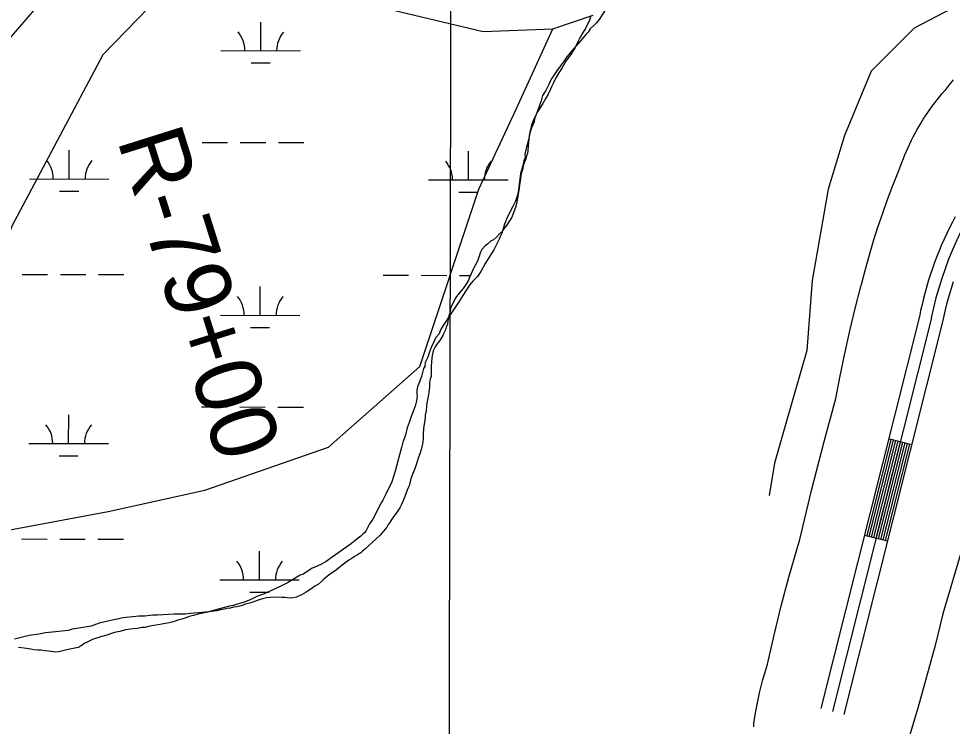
# Model space of a CAD drawing. Extents: x 3180038 to 3217926, y 922069 to 947485.
# Drawn here: x 3191568 to 3192742, y 934089 to 934979 of the extents above; entities that cross this region are included whole.
import ezdxf

# ---------------------------------------------------------------- set-up
doc = ezdxf.new("R2010")
doc.units = 0
for name, color, linetype in [('V-GRID-MAJR', 7, 'Continuous'), ('V-LEVE-TOET', 7, 'Continuous'), ('V-RIVR-RANG-IDEN', 7, 'Continuous'), ('V-ROAD-CNTR', 7, 'Continuous'), ('V-SITE-VEGE', 7, 'Continuous'), ('V-TOPO-SHOR', 7, 'Continuous'), ('V-WETL-SWMP', 7, 'Continuous')]:
    doc.layers.add(name, color=color, linetype=linetype)

msp = doc.modelspace()

# ---------------------------------------------------------------- linework, layer by layer
at = {"layer": 'V-GRID-MAJR'}
msp.add_spline([(3192093.7, 927501.1), (3192108.7, 933561.5), (3192123.6, 939624.6), (3192138.6, 945687.7), (3192138.6, 945690.3)], degree=3, dxfattribs=at)
at = {"layer": 'V-LEVE-TOET'}
for points in [[(3192667.4, 934769.2), (3192674.2, 934786.3), (3192677.2, 934793.7), (3192677.2, 934793.7), (3192678.9, 934798.5), (3192680.7, 934803.2), (3192682.6, 934807.9), (3192684.6, 934812.5), (3192686.6, 934817.1), (3192688.7, 934821.7), (3192690.9, 934826.2), (3192693.2, 934830.7), (3192695.6, 934835.2), (3192698, 934839.6), (3192700.5, 934844), (3192703.1, 934848.3), (3192705.7, 934852.6), (3192708.5, 934856.8), (3192711.3, 934861), (3192714.2, 934865.1), (3192717.1, 934869.2), (3192720.1, 934873.2), (3192723.2, 934877.2), (3192726.4, 934881.1), (3192729.6, 934885), (3192732.9, 934888.8), (3192733.1, 934889), (3192733.1, 934889), (3192738.4, 934895.6), (3192743.8, 934902.1)], [(3192492.5, 934088.7), (3192492.5, 934089.7), (3192492.6, 934090.8), (3192492.7, 934091.8), (3192492.7, 934092.9), (3192492.8, 934093.9), (3192493, 934095), (3192493.1, 934096), (3192493.3, 934097.1), (3192493.4, 934097.8), (3192493.4, 934097.8), (3192494.8, 934106.3), (3192496.4, 934114.7), (3192498.1, 934123.1), (3192500, 934131.5), (3192502, 934139.9), (3192504.2, 934148.2), (3192506.5, 934156.4), (3192508.9, 934164.7), (3192509.8, 934167.6), (3192509.8, 934167.6), (3192518.2, 934204.2), (3192527.2, 934240.7), (3192536.8, 934277), (3192547.1, 934313.1), (3192550.4, 934324.1), (3192550.4, 934324.1), (3192565.2, 934386), (3192581.1, 934447.6), (3192595.9, 934501.7), (3192595.9, 934501.7), (3192601.2, 934530), (3192607, 934558.3), (3192613.3, 934586.5), (3192620.1, 934614.6), (3192627.3, 934642.5), (3192628.4, 934646.4), (3192628.4, 934646.4), (3192633, 934664.2), (3192638, 934682), (3192643.3, 934699.6), (3192648.8, 934717.1), (3192654.7, 934734.6), (3192660.9, 934751.9), (3192667.4, 934769.2)], [(3192755.9, 934317.2), (3192730.3, 934230.7), (3192730.3, 934230.7), (3192720.5, 934191), (3192710, 934151.5), (3192698.8, 934112.2), (3192687, 934073.1)]]:
    msp.add_lwpolyline(points, dxfattribs=at)
at = {"layer": 'V-ROAD-CNTR'}
for p, q in [((3192691.2, 934443.5), (3192662.1, 934450.8)), ((3192660.8, 934322.2), (3192631.7, 934329.5))]:
    msp.add_line(p, q, dxfattribs=at)
for points in [[(3192745.9, 934730.1), (3192742.3, 934723.2), (3192738.7, 934716.2), (3192735.2, 934709), (3192732, 934701.8), (3192728.8, 934694.6), (3192725.8, 934687.4), (3192722.8, 934680), (3192720, 934672.6), (3192717.4, 934665.2), (3192714.9, 934657.7), (3192712.4, 934650.2), (3192710.2, 934642.6), (3192708.1, 934635.1), (3192706, 934627.4), (3192704.2, 934619.7), (3192702.4, 934612.1), (3192701.3, 934606.5), (3192577, 934111.8)], [(3192743.4, 934648.3), (3192741.1, 934641.3), (3192739, 934634.3), (3192737, 934627.2), (3192735.1, 934620.1), (3192733.4, 934612.9), (3192731.8, 934605.7), (3192730.5, 934599.8), (3192606, 934104.4)], [(3192715.9, 934603.1), (3192591.5, 934108.1)], [(3192665.1, 934450), (3192634.6, 934328.8)], [(3192668, 934449.3), (3192637.5, 934328.1)], [(3192670.9, 934448.6), (3192640.4, 934327.3)], [(3192673.8, 934447.8), (3192643.3, 934326.6)], [(3192676.7, 934447.1), (3192646.2, 934325.9)], [(3192679.6, 934446.4), (3192649.1, 934325.2)], [(3192682.5, 934445.7), (3192652.1, 934324.4)], [(3192685.4, 934444.9), (3192655, 934323.7)], [(3192688.3, 934444.2), (3192657.9, 934323)]]:
    msp.add_lwpolyline(points, dxfattribs=at)
msp.add_arc((3193144.3, 934516.5), 437.1, 141.7961, 168.5663, dxfattribs=at)
at = {"layer": 'V-SITE-VEGE'}
for points in [[(3192306.7, 934991.1), (3192298.4, 934978.3), (3192295, 934974), (3192291.7, 934970.6), (3192286.7, 934966.3), (3192284.2, 934962.1), (3192281.7, 934959.5), (3192275, 934951.8), (3192263.3, 934938.1), (3192260, 934933.9), (3192257.5, 934931.3), (3192254.2, 934926.2), (3192245.1, 934913.4), (3192237.6, 934902.3), (3192235.1, 934896.4), (3192231, 934888.7), (3192226.8, 934882.7), (3192225.2, 934875.9), (3192221.1, 934864.1), (3192217.1, 934853), (3192216.3, 934849.6), (3192213, 934842), (3192211.3, 934836.9), (3192208.9, 934825), (3192206.5, 934815.7), (3192204.9, 934808.9), (3192205, 934804.7), (3192203.3, 934800.4), (3192201.7, 934792.8), (3192199.3, 934784.3), (3192197, 934767.4), (3192196.2, 934761.4), (3192195.4, 934757.2), (3192193, 934749.6), (3192189.7, 934742.8), (3192183.1, 934730), (3192179, 934720.6), (3192176.5, 934712.2), (3192175.7, 934709.6), (3192174.1, 934706.2), (3192172.4, 934702), (3192165.8, 934688.4), (3192155, 934671.3), (3192149.3, 934661.1), (3192145.1, 934655.1), (3192139.3, 934649.1), (3192135.1, 934644), (3192126.8, 934631.2), (3192122.7, 934624.4), (3192112.7, 934609.1), (3192102.7, 934594.6), (3192098.6, 934587.7), (3192097, 934582.7), (3192092.8, 934578.4), (3192087, 934565.6), (3192084.6, 934558.8), (3192082.9, 934553.7), (3192079.6, 934546.9), (3192078.9, 934541.8), (3192077.2, 934539.3), (3192074.8, 934529.1), (3192071.5, 934520.6), (3192069.9, 934516.4), (3192069.1, 934512.1), (3192069.1, 934507.1), (3192069.2, 934504.5), (3192068.4, 934498.6), (3192066.8, 934491.8), (3192063.5, 934483.3), (3192061.9, 934479.1), (3192059.4, 934471.4), (3192057, 934464.6), (3192054.6, 934455.3), (3192051.3, 934446.8), (3192049.7, 934440), (3192047.3, 934430.7), (3192041.6, 934410.3), (3192037.5, 934396.7), (3192030.1, 934381.4), (3192026, 934373.8), (3192024.3, 934370.4), (3192013.6, 934349.9), (3192009.4, 934344)], [(3192009.4, 934344), (3192005.3, 934335.5), (3192003.7, 934332.9), (3192001.1, 934331.2), (3191998.6, 934328.6), (3191991.9, 934323.5), (3191986.9, 934319.2), (3191971, 934308), (3191962.6, 934302), (3191955.1, 934296.8), (3191949.2, 934293.3), (3191939.9, 934289), (3191937.4, 934288.1), (3191925.7, 934280.4), (3191922.3, 934279.5), (3191918.1, 934276.9), (3191906.4, 934270), (3191898, 934265.7), (3191876.9, 934256.1), (3191867.7, 934252.6), (3191859.3, 934248.3), (3191851.7, 934245.6), (3191838.2, 934241.2), (3191833.2, 934240.3), (3191812.9, 934235), (3191807, 934233.2), (3191794.4, 934232.2), (3191784.2, 934231.3), (3191777.5, 934230.3), (3191764, 934230.2), (3191742.8, 934229.1), (3191736.9, 934229), (3191726.8, 934228), (3191719.2, 934227.9), (3191699.8, 934226), (3191680.4, 934221.5), (3191669.4, 934218.9), (3191659.3, 934215.3), (3191644.1, 934212.6), (3191635.7, 934211.7), (3191630.6, 934209.9), (3191614.6, 934208), (3191601.9, 934207), (3191593.5, 934205.2), (3191581.7, 934203.4), (3191573.2, 934201.6), (3191563.1, 934198.9)]]:
    msp.add_lwpolyline(points, dxfattribs=at)
at = {"layer": 'V-TOPO-SHOR'}
for points in [[(3193241.5, 935291.6), (3193167.2, 935230.8), (3192836.2, 935041.6), (3192694.3, 934967.3), (3192640.3, 934913.3), (3192606.5, 934832.2), (3192586.2, 934764.7), (3192566, 934649.8), (3192559.2, 934562), (3192532.2, 934467.4), (3192518.7, 934420.1), (3192511.9, 934379.6)], [(3190821.2, 934111.9), (3190980, 934189.6), (3191125.3, 934334.8), (3191186.1, 934442.9), (3191257, 934547.6), (3191334.7, 934679.4), (3191402.3, 934784.1), (3191500.2, 934888.8), (3191588, 934990.1), (3191682.6, 935040.8), (3191804.2, 935067.8), (3191908.9, 935037.4), (3192023.8, 934993.5), (3192152.2, 934963.1), (3192240, 934966.5), (3192290.7, 934983.4)], [(3191804.2, 935067.8), (3191674.2, 934933.6), (3191559.3, 934717.4), (3191505.3, 934555.2), (3191451.2, 934426.9), (3191451.2, 934339), (3191498.5, 934325.5), (3191680.9, 934359.3), (3191802.5, 934386.3), (3191957.9, 934440.4), (3192072.8, 934541.7), (3192147.1, 934764.7), (3192194.4, 934866), (3192240, 934966.5)]]:
    msp.add_lwpolyline(points, dxfattribs=at)
at = {"layer": 'V-WETL-SWMP'}
for p, q in [((3191872.7, 934938.9), (3191872.8, 934974.9)), ((3191822.7, 934939), (3191922.7, 934938.8)), ((3191860.7, 934923.5), (3191884.7, 934923.4)), ((3191799, 934823.6), (3191831, 934823.6)), ((3191847, 934823.5), (3191879, 934823.4)), ((3191631.8, 934777.6), (3191631.9, 934813.6)), ((3191895, 934823.4), (3191927, 934823.3)), ((3192133.8, 934776.4), (3192133.8, 934812.4)), ((3191581.9, 934777.7), (3191681.8, 934777.5)), ((3192083.8, 934776.6), (3192183.8, 934776.3)), ((3191619.8, 934762.2), (3191643.8, 934762.1)), ((3192121.7, 934761), (3192145.7, 934761)), ((3191572.7, 934657.6), (3191604.7, 934657.6)), ((3191620.7, 934657.5), (3191652.7, 934657.5)), ((3191668.7, 934657.4), (3191700.7, 934657.4)), ((3192026.6, 934656.6), (3192058.6, 934656.5)), ((3192074.6, 934656.5), (3192106.6, 934656.4)), ((3192122.6, 934656.4), (3192136.3, 934656.4)), ((3191871.9, 934606.2), (3191872, 934642.2)), ((3191821.9, 934606.3), (3191921.9, 934606.1)), ((3191859.9, 934590.8), (3191883.9, 934590.8)), ((3191798.3, 934491), (3191830.3, 934490.9)), ((3191846.3, 934490.9), (3191878.3, 934490.8)), ((3191894.3, 934490.7), (3191926.3, 934490.7)), ((3191631.1, 934444.9), (3191631.2, 934480.9)), ((3191581.1, 934445), (3191681.1, 934444.8)), ((3191619.1, 934429.5), (3191643.1, 934429.5)), ((3191572, 934325), (3191604, 934324.9)), ((3191620, 934324.9), (3191652, 934324.8)), ((3191668, 934324.8), (3191700, 934324.7)), ((3191871.2, 934273.6), (3191871.3, 934309.6)), ((3191821.2, 934273.7), (3191921.2, 934273.4)), ((3191859.1, 934258.2), (3191883.1, 934258.1))]:
    msp.add_line(p, q, dxfattribs=at)
for points in [[(3192287.6, 934982.5), (3192286.1, 934977.3), (3192281, 934966.7)], [(3192281, 934966.7), (3192276.6, 934959.8), (3192275.8, 934958.6), (3192273.8, 934954.9), (3192271.9, 934950.9), (3192267.6, 934942), (3192265.6, 934939.1), (3192262.4, 934934.2), (3192256.5, 934925.7), (3192252.5, 934918.8), (3192250.2, 934914.7), (3192247.4, 934911.1), (3192243.8, 934904.6), (3192240.7, 934898.5), (3192238.3, 934893.6), (3192237.2, 934890.4), (3192234, 934884.3), (3192231.2, 934879), (3192227.3, 934872.5), (3192223.7, 934866.8), (3192220.6, 934862), (3192215.5, 934851.8), (3192213.1, 934845.3), (3192211.2, 934836.8), (3192210.1, 934831.2), (3192209.4, 934823.5), (3192208.7, 934813.4), (3192207.9, 934809.8), (3192206.7, 934806.6), (3192205.6, 934802.1), (3192202.5, 934794), (3192202.1, 934790.8), (3192199.8, 934782.7), (3192199.4, 934778.2), (3192198.7, 934775), (3192197.9, 934769.8), (3192197.2, 934762.9), (3192196.1, 934756.4), (3192194.9, 934750.8), (3192193.4, 934743.1), (3192190.7, 934735), (3192188, 934728.9), (3192183.6, 934722.4), (3192181.6, 934719.2), (3192179.2, 934716.3), (3192177.3, 934712.7), (3192172.9, 934708.6), (3192169.3, 934704.5), (3192165.3, 934701.2), (3192162.5, 934699.6), (3192157.7, 934695.5), (3192154.9, 934693.4), (3192150.5, 934688.9), (3192149, 934685.7), (3192147, 934679.2), (3192145.1, 934674.4), (3192141.5, 934667.5), (3192139.6, 934664.2), (3192136.8, 934657.3), (3192132.9, 934648.8), (3192129.7, 934643.5), (3192127, 934639.9), (3192120.2, 934631.7), (3192117.8, 934628.5), (3192115.1, 934623.2), (3192113.9, 934620), (3192111.9, 934616.3), (3192110.4, 934609.4), (3192109.3, 934605.4), (3192108.1, 934599.3), (3192107.4, 934594.9), (3192105.8, 934591.2), (3192105, 934588), (3192103.9, 934585.2), (3192101.9, 934581.9), (3192101.5, 934580.7), (3192099.1, 934576.6), (3192096, 934572.6), (3192094, 934569.7), (3192092, 934566.5), (3192089.6, 934561.6), (3192088.1, 934555.5), (3192087.7, 934551.9), (3192087.4, 934547.9), (3192087.1, 934541.4), (3192086.8, 934533.3), (3192086.8, 934529.3), (3192085.6, 934526.1), (3192084.9, 934521.2), (3192085, 934516.4), (3192084.2, 934509.1), (3192083.1, 934503.9), (3192082.3, 934499.8), (3192081.6, 934496.2), (3192081.2, 934492.1), (3192080.5, 934486.1), (3192079.3, 934480.8), (3192079.4, 934477.6), (3192078.7, 934471.6), (3192077.5, 934464.3), (3192076.8, 934456.2)], [(3192076.8, 934456.2), (3192076.9, 934451.8), (3192076.5, 934446.5), (3192075.4, 934440.9), (3192074.6, 934437.6), (3192072.7, 934432), (3192070.7, 934426.7), (3192068, 934418.2), (3192064.9, 934408.9), (3192063.7, 934406.9), (3192063, 934405.2), (3192061.4, 934400.4), (3192059.1, 934391.9), (3192057.9, 934389.1), (3192056.7, 934386.2), (3192054, 934378.5), (3192051.3, 934372), (3192049.3, 934367.6), (3192047.7, 934363.9), (3192045, 934360.3), (3192037.4, 934349.7), (3192035.1, 934345.6), (3192033.1, 934343.2), (3192031.1, 934339.9), (3192027.1, 934334.7), (3192022.8, 934329.8), (3192017.6, 934324.9), (3192008.4, 934316.7), (3192004.8, 934313), (3192000.8, 934309.7), (3191998.4, 934307.7), (3191994.4, 934304.8), (3191991.6, 934303.2), (3191986.4, 934299.9), (3191983.6, 934298.2), (3191980, 934295.8), (3191974.9, 934292.1), (3191970.9, 934288.8), (3191967.7, 934285.9), (3191964.1, 934283.5), (3191958.9, 934279.8), (3191954.1, 934276.1), (3191951.3, 934273.6), (3191948.9, 934271.6), (3191945.3, 934268.3), (3191941.7, 934265.9), (3191938.9, 934264.2), (3191935.7, 934261.8), (3191929.7, 934258.1), (3191924.1, 934254.8), (3191917.7, 934251.9), (3191913.7, 934251), (3191908.8, 934250.5), (3191902.8, 934251.3), (3191899.2, 934251.2), (3191890.3, 934251.9), (3191884.6, 934251.4), (3191879.8, 934251), (3191875, 934249.7), (3191869.4, 934248), (3191860.1, 934244.7), (3191856.9, 934243.8), (3191853.7, 934243), (3191848.1, 934240.9), (3191842.5, 934239.6), (3191838.4, 934239.2), (3191834.4, 934237.9), (3191830.4, 934237.5), (3191827.2, 934236.6), (3191821.9, 934235.8), (3191817.5, 934234.5), (3191813.9, 934234), (3191810.3, 934233.6), (3191806.3, 934233.1), (3191801.8, 934231.9), (3191798.2, 934231.4), (3191794.2, 934230.6), (3191788.2, 934228.9), (3191782.5, 934227.6), (3191779.7, 934226.4), (3191773.3, 934224.3), (3191769.3, 934223.4), (3191766.5, 934222.2), (3191760.9, 934220.5), (3191757.6, 934219.6), (3191752.8, 934218.8), (3191746, 934217.5), (3191741.1, 934216.6), (3191737.9, 934216.2), (3191731.5, 934214.9), (3191727.1, 934213.6), (3191723.4, 934213.6), (3191717.8, 934212.3), (3191712.2, 934211.8), (3191702.5, 934210.5), (3191695.3, 934208.8), (3191688.8, 934207.5), (3191685.2, 934206.2), (3191679.2, 934204.2), (3191674.4, 934202.9), (3191671.2, 934202)], [(3191671.2, 934202), (3191668, 934200.8), (3191663.1, 934199.5), (3191660.3, 934198.3), (3191654.3, 934195.4), (3191651.5, 934194.1), (3191646.7, 934190.8), (3191643.1, 934188.4), (3191639.1, 934187.5), (3191632.7, 934186.6), (3191625.4, 934184.9), (3191620.6, 934183.3), (3191615, 934182.8), (3191605.7, 934183.9), (3191601.7, 934184.2), (3191596, 934185), (3191592.4, 934185.3), (3191587.5, 934185.7), (3191583.5, 934186.4), (3191575.4, 934187.5), (3191568.1, 934188.3)]]:
    msp.add_lwpolyline(points, dxfattribs=at)
for centre, start, end in [((3191817.4, 934939.5), 359.099, 40.6427), ((3191927.9, 934939.2), 139.099, 180.6426), ((3191576.6, 934778.2), 359.099, 40.6427), ((3191687.1, 934777.9), 139.099, 180.6426), ((3192078.5, 934777), 359.099, 40.6427), ((3192189, 934776.8), 139.099, 180.6426), ((3191816.7, 934606.8), 359.099, 40.6427), ((3191927.2, 934606.6), 139.099, 180.6426), ((3191575.9, 934445.5), 359.099, 40.6427), ((3191686.3, 934445.3), 139.099, 180.6426), ((3191815.9, 934274.2), 359.099, 40.6427), ((3191926.4, 934273.9), 139.099, 180.6426)]:
    msp.add_arc(centre, 35.2, start, end, dxfattribs=at)

# ---------------------------------------------------------------- texts
at = {"layer": 'V-RIVR-RANG-IDEN'}
msp.add_text('R-79+00', height=83, rotation=287.4634, dxfattribs=at).set_placement((3191691.8, 934826.9))

doc.saveas('drawing.dxf')
